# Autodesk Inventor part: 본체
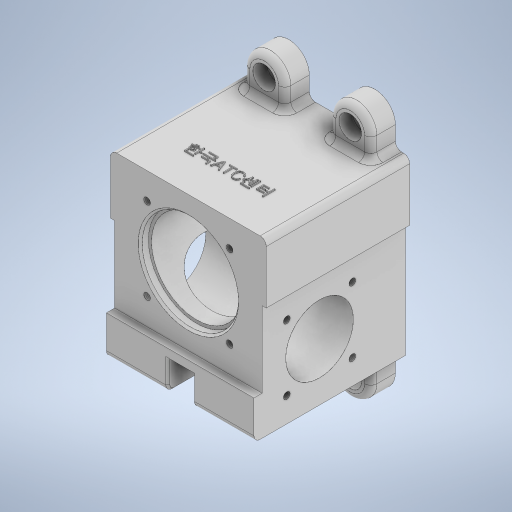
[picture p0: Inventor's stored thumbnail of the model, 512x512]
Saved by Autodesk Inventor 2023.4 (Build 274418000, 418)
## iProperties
Created: 2024-11
Part Number: 본체
Material: 일반
Document SubType Name: Modeling
Designer: EDU
Density: 1 g/cm^3
Appearance: 기본값
Author: EDU
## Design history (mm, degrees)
sketch "스케치1"
  geometry: L1 (-38, 42.5)-(38, 42.5); L2 (38, 42.5)-(38, -42.5); L3 (38, -42.5)-(-38, -42.5); L4 (-38, -42.5)-(-38, 42.5); 3 further points
  constraints: 8 end point, 2 midpoint, 2 parallel, 1 horizontal, 1 horizontal alignment, 1 perpendicular, 1 vertical alignment
  dimensions: "d0" = 76 distance between parallel lines of L2 L4; "d1" = 85 distance between parallel lines of L3 L1
extrude "돌출1" new body sketch "스케치1" distance "d2" = 74; taper "d3" = 0 deg
sketch "스케치2"
  geometry: L1 (-38, -42.5)-(38, -42.5) reference; L2 (38, -42.5)-(38, 42.5) reference; L3 (38, 42.5)-(-38, 42.5) reference; L4 (-38, 42.5)-(-38, -42.5) reference; L5 (-38, -42.5)-(38, -42.5) reference; L6 (-6, -42.5)-(-6, -27.5); L7 (-6, -27.5)-(6, -27.5); L8 (6, -27.5)-(6, -42.5); 4 further points
  constraints: 6 end point, 2 perpendicular, 2 point on line, 1 midpoint, 1 vertical, 1 vertical alignment
  dimensions: "d4" = 15 distance between parallel lines of L1 L7; "d5" = 12 distance between parallel lines of L8 L6
extrude "돌출2" cut sketch "스케치2" stored distance "d6" = 74; taper "d7" = 0 deg
sketch "스케치3"
  geometry: L1 (0, 85)-(0, 0) reference; L2 (0, 0)-(74, 0) reference; L3 (74, 85)-(74, 0) reference; L4 (0, 85)-(74, 85) reference; L5 (0, 85)-(74, 85) reference; L6 (70, 85)-(70, 19); L7 (70, 19)-(74, 19); L8 (74, 0)-(74, 85) reference; 3 further points
  constraints: 4 end point, 2 point on line, 1 perpendicular, 1 vertical
  dimensions: "d8" = 66 distance between parallel lines of L7 L4; "d9" = 4 distance between parallel lines of L3 L6
extrude "돌출3" cut sketch "스케치3" stored distance "d10" = 10; taper "d11" = 0 deg
sketch "스케치4"
  geometry: L1 (38, -23.5)-(-38, -23.5) reference; L2 (-38, -23.5)-(-38, -42.5) reference; L3 (-38, -42.5)-(-6, -42.5) reference; L4 (-6, -42.5)-(-6, -27.5) reference; L5 (-6, -27.5)-(6, -27.5) reference; L6 (6, -27.5)-(6, -42.5) reference; L7 (6, -42.5)-(38, -42.5) reference; L8 (38, -42.5)-(38, -23.5) reference; L9 (6, -42.5)-(38, -42.5) reference; L10 (36, -42.5)-(36, 13.5); L11 (36, 13.5)-(38, 13.5); L12 (-38, -42.5)-(-6, -42.5) reference; L13 (-36, -42.5)-(-36, 13.5); L14 (-36, 13.5)-(-38, 13.5); L15 (38, 42.5)-(38, -23.5) reference; L16 (-38, 42.5)-(38, 42.5) reference; L17 (-38, -23.5)-(-38, 42.5) reference; L18 (-38, -23.5)-(38, -23.5) reference; 7 further points
  constraints: 8 end point, 3 perpendicular, 2 point on line, 1 vertical
  dimensions: "d12" = 56 distance between parallel lines of L7 L11; "d13" = 56 distance between parallel lines of L3 L14; "d14" = 2 distance between parallel lines of L13 L2; "d15" = 2 distance between parallel lines of L10 L8
extrude "돌출4" cut sketch "스케치4" stored distance "d16" = 10; taper "d17" = 0 deg
sketch "스케치5"
  geometry: L1 (74, -66)-(74, -29) reference; L2 (74, -29)-(76, -29) reference; L3 (76, 0)-(76, -29) reference; L4 (0, 0)-(76, 0) reference; L5 (0, -29)-(0, 0) reference; L6 (0, -29)-(2, -29) reference; L7 (2, -29)-(2, -66) reference; L8 (2, -66)-(74, -66) reference; C1 r 23.5 at (38, -33); 1 further point
  constraints: 1 centre point
  dimensions: "d18" = 47 diameter of C1; "d19" = 33 distance from line of C1.centre L4
extrude "돌출5" cut sketch "스케치5" distance "d20" = 4; taper "d21" = 0 deg
sketch "스케치6"
  geometry: C1 r 23.5 at (0, 9.5) reference; C2 r 22 at (0, 9.5); 1 further point
  constraints: 1 centre point, 1 coincident
  dimensions: "d22" = 44 diameter of C2
extrude "돌출6" cut sketch "스케치6" distance "d23" = 56; taper "d24" = 0 deg
sketch "스케치7"
  geometry: C1 r 22 at (0, 0) reference; C2 r 17.5 at (0, 0); 1 further point
  constraints: 1 centre point, 1 coincident
  dimensions: "d25" = 35 diameter of C2
extrude "돌출7" cut sketch "스케치7" distance "d26" = 11; taper "d27" = 0 deg
sketch "스케치8"
  geometry: C1 r 17.5 at (0, 0) reference; C2 r 15 at (0, 0); 1 further point
  constraints: 1 centre point, 1 coincident
  dimensions: "d28" = 30 diameter of C2
extrude "돌출8" cut sketch "스케치8" distance "d29" = 3; taper "d30" = 0 deg
fillet "모깎기1" dims "d31" = 3
fillet "모깎기2" dims "d32" = 0.6
chamfer "모따기1" distance "d33" = 1; stored, may be unused: second distance "d34" = 2, angle "d35" = 45 deg
fillet "모깎기3" dims "d36" = 3
chamfer "모따기2" distance "d37" = 1; stored, may be unused: second distance "d38" = 2, angle "d39" = 45 deg
sketch "스케치9"
  geometry: L1 (-74, 56)-(-4, 56) reference; L2 (-4, 56)-(-4, 85) reference; L3 (-74, 85)-(-4, 85) reference; L4 (-74, 85)-(-74, 56) reference; L5 (-4, 19)-(0, 19) reference; L6 (-4, 56)-(-4, 19) reference; L7 (-4, 56)-(-74, 56) reference; L8 (-74, 0)-(-74, 56) reference; L9 (0, 0)-(-74, 0) reference; L10 (0, 19)-(0, 0) reference; C1 r 16.5 at (-32, 28); 1 further point
  constraints: 1 centre point
  dimensions: "d40" = 33 diameter of C1; "d41" = 57 distance from line of C1.centre L3; "d42" = 42 distance from line of L8 C1.centre
extrude "돌출9" cut sketch "스케치9" stored distance "d43" = 3; taper "d44" = 0 deg
sketch "스케치10"
  geometry: L1 (-36, 13.5)-(-36, -42.5) reference; L2 (-6, -42.5)-(-36, -42.5) reference; L3 (-6, -42.5)-(-6, -27.5) reference; L4 (-6, -27.5)-(6, -27.5) reference; L5 (6, -27.5)-(6, -42.5) reference; L6 (36, -42.5)-(6, -42.5) reference; L7 (36, -42.5)-(36, 13.5) reference; L8 (36, 13.5)-(38, 13.5) reference; L9 (38, 42.5)-(38, 13.5) reference; L10 (-38, 42.5)-(38, 42.5) reference; L11 (-38, 13.5)-(-38, 42.5) reference; L12 (-38, 13.5)-(-36, 13.5) reference; L13 (-31, 52.5)-(-31, 42.5); L14 (38, 42.5)-(-38, 42.5) reference; L15 (-11, 52.5)-(-11, 42.5); L16 (11, 52.5)-(11, 42.5); L17 (31, 52.5)-(31, 42.5); L18 (-38, 42.5)-(38, 42.5) reference; A1 r 10 centre (-21, 52.5) between (-31, 52.5) and (-11, 52.5); A2 r 10 centre (21, 52.5) between (11, 52.5) and (31, 52.5); 6 further points
  constraints: 8 end point, 5 point on line, 4 point on circle, 4 tangent, 2 centre point, 2 parallel, 2 perpendicular, 1 horizontal alignment, 1 midpoint
  dimensions: "d45" = 20 diameter of A1; "d46" = 20 diameter of A2; "d47" = 21 horizontal distance of point (0, 42.5) A1.centre; "d48" = 42 distance of A2.centre A1.centre; "d49" = 10 distance from line of L10 A1.centre
extrude "돌출10" join sketch "스케치10" distance "d50" = 12; taper "d51" = 0 deg
sketch "스케치11"
  geometry: L1 (-11, 42.5)-(-11, 52.5) reference; L2 (-31, 52.5)-(-31, 42.5) reference; L3 (-11, 42.5)-(-31, 42.5) reference; L4 (31, 42.5)-(31, 52.5) reference; L5 (11, 52.5)-(11, 42.5) reference; L6 (31, 42.5)-(11, 42.5) reference; C1 r 5.5 at (-21, 52.5); C2 r 5.5 at (21, 52.5); A1 r 10 centre (-21, 52.5) between (-11, 52.5) and (-31, 52.5) reference; A2 r 10 centre (21, 52.5) between (31, 52.5) and (11, 52.5) reference; 1 further point
  constraints: 2 centre point, 2 coincident
  dimensions: "d52" = 11 diameter of C1; "d53" = 11 diameter of C2
extrude "돌출11" cut sketch "스케치11" distance "d54" = 6.6; taper "d55" = 0 deg
sketch "스케치12"
  geometry: C1 r 5.5 at (0, 0) reference; C2 r 5.5 at (42, 0) reference; C3 r 3.3 at (0, 0); C4 r 5.5 at (42, 0) reference; C5 r 3.3 at (42, 0); 1 further point
  constraints: 2 centre point, 2 coincident
  dimensions: "d56" = 6.6 diameter of C3; "d57" = 6.6 diameter of C5
extrude "돌출12" cut sketch "스케치12" stored distance "d58" = 6.6; taper "d59" = 0 deg
sketch "스케치13" dims "d60" = 57
  geometry: L1 (74, -66)-(74, -29) reference; L2 (74, -29)-(76, -29) reference; L3 (76, 0)-(76, -29) reference; L4 (0, 0)-(76, 0) reference; L5 (0, -29)-(0, 0) reference; L6 (0, -29)-(2, -29) reference; L7 (2, -29)-(2, -66) reference; L8 (2, -66)-(74, -66) reference; L9 (-45.472, -33)-(121.472, -33); L10 (-7.993, -78.993)-(83.993, 12.993); C1 r 24.5 at (38, -33) reference; 4 further points
  constraints: 4 end point, 2 coincident, 2 midpoint, 1 horizontal, 1 point on line, 3 other
  dimensions: "d61" = 45 deg angle of L9 L10
hole "구멍1" sketch "스케치13" at (58.153, -12.847) diameter "d62" = 3.242; stored, may be unused: countersink angle "d66" = 82 deg, drill point angle "d68" = 118 deg; dims "d63" = 8, "d64" = 3.023, "d65" = 2, "d67" = 10
sketch "스케치14"
  geometry: C1 r 16.5 at (-32, 28) reference; 5 further points
  constraints: 1 vertical alignment
  dimensions: "d72" = 16 horizontal distance of C1.centre point (-48, 44); "d73" = 32 distance of point (-48, 12) point (-48, 44); "d74" = 16 horizontal distance of C1.centre point (-16, 44); "d75" = 32 distance of point (-16, 12) point (-16, 44); "d76" = 32 distance of point (-48, 44) point (-16, 44); "d77" = 32 distance of point (-16, 12) point (-48, 12); "d78" = 16 horizontal distance of C1.centre point (-16, 12)
hole "구멍2" sketch "스케치14" at (-48, 44), (-48, 12), (-16, 44), (-16, 12) diameter "d79" = 3.242; stored, may be unused: countersink angle "d83" = 90 deg, drill point angle "d85" = 118 deg; dims "d80" = 8, "d81" = 4, "d82" = 2, "d84" = 10
sketch "스케치15"
  geometry: L1 (0, 0)-(76, 0) reference; L2 (49, 70)-(27, 70) reference; 3 further points
  constraints: 1 midpoint, 1 vertical alignment, 1 other
  dimensions: "d86" = 20 distance from line of L1 point (38, 20)
feature "엠보싱1" sketch "스케치15" dims "d87" = 0.5, "d88" = 0
sketch "스케치16"
  geometry: L1 (0, -21.839)-(12, -21.839) reference; L2 (12, 0)-(12, -21.839) reference; L3 (0, 0)-(12, 0) reference; L4 (0, 0)-(0, -21.839) reference; L5 (12, -42.161)-(0, -42.161) reference; L6 (0, -42.161)-(0, -74) reference; L7 (12, -74)-(0, -74) reference; L8 (12, -42.161)-(12, -74) reference; 4 further points
  constraints: 2 vertical alignment, 1 midpoint
  dimensions: "d89" = 12 distance from line of point (6, -12) L3; "d90" = 40 distance of point (6, -52) point (6, -12)
hole "구멍3" sketch "스케치16" at (6, -12), (6, -52) diameter "d91" = 3.242; stored, may be unused: countersink angle "d95" = 90 deg, drill point angle "d97" = 118 deg; dims "d92" = 8, "d93" = 4, "d94" = 2, "d96" = 10
fillet "모깎기4" dims "d98" = 3
fillet "모깎기5" dims "d99" = 3
fillet "모깎기6" dims "d100" = 3
fillet "모깎기7" dims "d101" = 3
chamfer "모따기3" distance "d102" = 1; stored, may be unused: second distance "d103" = 2, angle "d104" = 45 deg
chamfer "모따기4" distance "d105" = 1; stored, may be unused: second distance "d106" = 2, angle "d107" = 45 deg
node "솔리드1"
mirror "미러1"
pattern_circular "원형 패턴1" dims angle "d70" = 360 deg
mirror "미러2"
mirror "미러3"
node "투영된 루프1"
node "투영된 루프2"
node "투영된 루프3"
node "투영된 루프4"
node "투영된 루프5"
node "투영된 루프6"
node "투영된 루프7"
node "투영된 루프8"
node "투영된 루프9"
node "투영된 루프10"
node "투영된 루프11"
node "투영된 루프12"
node "투영된 루프13"
node "투영된 루프14"
node "투영된 루프15"
node "투영된 루프16"
node "투영된 루프17"
node "투영된 루프18"
feature "A9D066F2-1C7D-4E18-AEED-F7BC21143FA4" dims "d79" = 3.242, "d80" = 8, "d81" = 4, "d82" = 2, "d83" = 90 deg, "d84" = 10, "d85" = 118 deg
